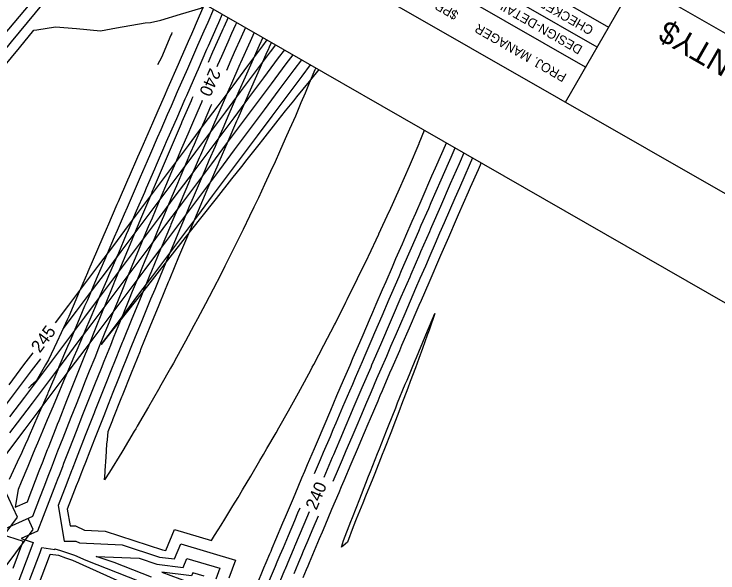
# Model space of a CAD drawing. Extents: x 1160447 to 1162032, y 616022 to 618272.
# Drawn here: x 1160997.8 to 1161139.1, y 616733 to 616845.1 of the extents above; entities that cross this region are included whole.
import ezdxf

# ---------------------------------------------------------------- set-up
doc = ezdxf.new("R2010")
doc.units = 0
for name, color, linetype in [('BORDER', 7, 'Continuous'), ('BRIDGE_TITLE', 7, 'Continuous'), ('D_Contours_Major', 7, 'Continuous'), ('D_Contours_Minor', 7, 'Continuous'), ('Plot Boundary_1', 7, 'Continuous')]:
    doc.layers.add(name, color=color, linetype=linetype)

msp = doc.modelspace()

# ---------------------------------------------------------------- linework, layer by layer
at = {"layer": 'BORDER'}
for p, q in [((1161303.72, 616715.44), (1160848.31, 616976.65)), ((1161108.53, 616827.39), (1161133.41, 616870.77)), ((1161274.24, 616764.57), (1161122.44, 616851.64))]:
    msp.add_line(p, q, dxfattribs=at)
for points in [[(1161041.29, 616886.02), (1161117.17, 616842.49)], [(1161114.86, 616838.45), (1161038.97, 616881.98)], [(1161112.54, 616834.41), (1161039.71, 616876.18)]]:
    msp.add_lwpolyline(points, dxfattribs=at)
at = {"layer": 'D_Contours_Major'}
for points in [[(1160975.33, 616809.76), (1160976.62, 616811.32), (1160979.81, 616815.18), (1160982.99, 616819.04), (1160986.17, 616822.9), (1160989.36, 616826.76), (1160992.55, 616830.62), (1160995.73, 616834.47), (1160998.92, 616838.33), (1161001.83, 616841.84), (1161002.43, 616841.94), (1161006.15, 616842.54), (1161010.36, 616842.17), (1161015.21, 616841.72), (1161018.4, 616842.3), (1161024.16, 616843.33), (1161025.22, 616843.37), (1161027.33, 616843.88), (1161031.24, 616845.06), (1161035.35, 616846.28), (1161036.36, 616846.96)], [(1161037.88, 616846.09), (1161036.7, 616843.4), (1161035.94, 616841.67), (1161034.66, 616838.77), (1161033.84, 616836.91), (1161032.63, 616834.13), (1161030.6, 616829.5), (1161029.34, 616826.6), (1161028.58, 616824.86), (1161027.28, 616821.88), (1161026.56, 616820.23), (1161025.22, 616817.15), (1161024.54, 616815.59), (1161023.17, 616812.4), (1161022.53, 616810.94), (1161021.13, 616807.7), (1161020.53, 616806.3), (1161019.93, 616804.92), (1161018.53, 616801.66), (1161017.94, 616800.3), (1161016.53, 616797.01), (1161015.96, 616795.69), (1161014.53, 616792.36), (1161013.98, 616791.07), (1161012.55, 616787.71), (1161012.01, 616786.46), (1161010.56, 616783.05), (1161009.01, 616779.41), (1161008.58, 616778.4), (1161006.83, 616774.29), (1161006.6, 616773.74), (1161004.74, 616769.34), (1161004.63, 616769.09), (1161004.53, 616768.86), (1161002.61, 616764.45), (1161000.9, 616760.5), (1161000.59, 616759.8), (1161000.1, 616758.66), (1160999.56, 616757.49), (1160999.38, 616757.1), (1160998.49, 616755.2), (1160996.89, 616751.74)], [(1161038.61, 616834.58), (1161038.76, 616834.9), (1161039.52, 616836.63), (1161040.8, 616839.52), (1161041.56, 616841.24), (1161042.34, 616842.97), (1161042.53, 616843.42)], [(1161048.6, 616839.94), (1161047.71, 616838.74), (1161044.72, 616834.73), (1161041.73, 616830.72), (1161038.74, 616826.71), (1161035.75, 616822.71), (1161032.76, 616818.7), (1161029.76, 616814.7), (1161026.77, 616810.69), (1161023.77, 616806.69), (1161020.77, 616802.69), (1161017.78, 616798.68), (1161014.78, 616794.68), (1161011.78, 616790.68), (1161008.77, 616786.68), (1161006.09, 616783.11)], [(1161059.02, 616833.96), (1161057.07, 616831.57), (1161054.54, 616828.46), (1161053.91, 616827.69), (1161052.27, 616825.66), (1161050.78, 616823.79), (1161047.68, 616819.86), (1161046.96, 616818.95), (1161044.58, 616815.94), (1161043.48, 616814.54), (1161041.48, 616812.01), (1161038.39, 616808.09), (1161035.29, 616804.16), (1161032.2, 616800.23), (1161029.11, 616796.3), (1161026.01, 616792.37), (1161022.92, 616788.44), (1161019.83, 616784.51), (1161018.66, 616783.02), (1161016.75, 616780.58), (1161015.35, 616778.79), (1161016.71, 616780.6), (1161019.71, 616784.6), (1161022.71, 616788.6), (1161025.71, 616792.6), (1161028.71, 616796.6), (1161031.71, 616800.61), (1161034.71, 616804.61), (1161037.7, 616808.61), (1161040.69, 616812.62), (1161043.69, 616816.62), (1161046.68, 616820.63), (1161049.67, 616824.64), (1161052.66, 616828.65), (1161055.65, 616832.66), (1161057.34, 616834.93)], [(1161035.61, 616827.74), (1161035.46, 616827.38), (1161034.71, 616825.65), (1161033.45, 616822.75), (1161032.7, 616821.02), (1161031.45, 616818.11), (1161030.21, 616815.22), (1161029.46, 616813.47), (1161028.23, 616810.58), (1161027.49, 616808.82), (1161026.74, 616807.06), (1161025.53, 616804.17), (1161024.78, 616802.39), (1161023.58, 616799.52), (1161022.83, 616797.71), (1161021.64, 616794.85), (1161020.47, 616792.02), (1161019.72, 616790.19), (1161018.57, 616787.38), (1161017.8, 616785.51), (1161017.04, 616783.63), (1161015.9, 616780.84), (1161014.79, 616778.08), (1161014.02, 616776.15), (1161012.93, 616773.43), (1161012.14, 616771.47), (1161011.35, 616769.47), (1161010.28, 616766.77), (1161009.23, 616764.12), (1161008.43, 616762.08), (1161007.62, 616760), (1161006.59, 616757.37), (1161006.18, 616756.32), (1161005.68, 616755.02), (1161005.26, 616753.95), (1161004.76, 616752.67), (1161003.79, 616750.14), (1161002.95, 616747.96), (1161001.54, 616744.28), (1160995.35, 616741.48)], [(1161088.13, 616817.26), (1161087.38, 616815.54), (1161087.15, 616815.03), (1161085.39, 616811), (1161083.4, 616806.46), (1161081.64, 616802.43), (1161081.42, 616801.92), (1161081.19, 616801.41), (1161079.44, 616797.38), (1161079.22, 616796.87), (1161077.46, 616792.83), (1161077.25, 616792.33), (1161075.49, 616788.28), (1161073.73, 616784.2), (1161073.53, 616783.73), (1161073.33, 616783.27), (1161071.57, 616779.18), (1161071.38, 616778.74), (1161069.61, 616774.63), (1161069.43, 616774.21), (1161067.66, 616770.07), (1161065.86, 616765.88), (1161065.71, 616765.52), (1161063.9, 616761.29), (1161063.76, 616760.96), (1161061.94, 616756.69), (1161061.82, 616756.4), (1161061.7, 616756.11), (1161060, 616752.11)], [(1161001.6, 616777.14), (1160999.76, 616774.69), (1160996.76, 616770.7)], [(1161057.09, 616745.23), (1161056.02, 616742.71), (1161054.14, 616738.25), (1161054.09, 616738.14), (1161054.07, 616738.08), (1161053.13, 616735.85), (1161052.18, 616733.6), (1161052.17, 616733.57), (1161052.15, 616733.51), (1161050.26, 616729)], [(1160992.71, 616729.7), (1161001.7, 616741.71), (1161000.68, 616743.9)], [(1160995.08, 616740.79), (1160999.65, 616739.35), (1160999.34, 616738.53), (1160997.56, 616733.84)], [(1161036.01, 616732.31), (1161033.72, 616732.98), (1161033.46, 616732.36), (1161027.47, 616733.11), (1161032.93, 616731.08)]]:
    msp.add_lwpolyline(points, dxfattribs=at)
at = {"layer": 'D_Contours_Minor'}
for points in [[(1160995.75, 616840.76), (1160998.94, 616844.62), (1161002.13, 616848.47), (1161005.32, 616852.32), (1161008.52, 616856.17), (1161011.71, 616860.03), (1161012.31, 616860.75)], [(1160973.79, 616811.03), (1160975.04, 616812.54), (1160978.22, 616816.4), (1160981.4, 616820.26), (1160984.59, 616824.12), (1160987.77, 616827.98), (1160990.96, 616831.83), (1160994.15, 616835.69), (1160997.34, 616839.55), (1161000.53, 616843.4), (1161003.72, 616847.25), (1161006.91, 616851.11), (1161010.1, 616854.96), (1161013.3, 616858.81), (1161014.07, 616859.74)], [(1161035.95, 616846.81), (1161034.82, 616844.23), (1161033.44, 616841.05), (1161032.81, 616839.58), (1161031.2, 616835.91), (1161030.78, 616834.95), (1161028.73, 616830.31), (1161027.96, 616828.55), (1161026.7, 616825.68), (1161025.61, 616823.2), (1161024.66, 616821.05), (1161023.26, 616817.84), (1161022.63, 616816.41), (1161020.92, 616812.48), (1161020.61, 616811.77), (1161018.71, 616807.41), (1161018.59, 616807.13), (1161018.48, 616806.87), (1161016.58, 616802.48), (1161016.53, 616802.35), (1161014.59, 616797.86), (1161014.58, 616797.83), (1161012.65, 616793.36), (1161012.57, 616793.18), (1161010.72, 616788.89), (1161010.57, 616788.53), (1161008.8, 616784.42), (1161008.57, 616783.88), (1161008.15, 616782.98), (1161006.45, 616779.28), (1161004.74, 616775.71), (1161004.18, 616774.74), (1161002.29, 616771.47), (1161001.23, 616770.47), (1161000.77, 616770.04)], [(1161039.63, 616845.09), (1161038.85, 616843.33), (1161038.53, 616842.59), (1161036.8, 616838.67), (1161036.49, 616837.96), (1161034.76, 616834.01), (1161034.46, 616833.33), (1161032.43, 616828.7), (1161032.12, 616827.99), (1161030.41, 616824.07), (1161030.09, 616823.33), (1161028.39, 616819.43), (1161028.06, 616818.67), (1161026.38, 616814.8), (1161026.03, 616813.99), (1161024.37, 616810.16), (1161024.01, 616809.32), (1161022.37, 616805.52), (1161020.75, 616801.76), (1161020.37, 616800.88), (1161018.77, 616797.15), (1161018.37, 616796.23), (1161016.79, 616792.54), (1161016.38, 616791.59), (1161014.82, 616787.94), (1161014.39, 616786.94), (1161012.86, 616783.34), (1161012.41, 616782.29), (1161011.93, 616781.16), (1161010.43, 616777.64), (1161009.87, 616776.32), (1161008.45, 616772.98), (1161007.79, 616771.42), (1161006.48, 616768.33), (1161005.69, 616766.45), (1161004.51, 616763.67), (1161003.57, 616761.43), (1161002.55, 616759.01), (1161002.03, 616757.77), (1161001.57, 616756.68), (1161001.01, 616755.33), (1161000.59, 616754.35), (1160999.26, 616751.16), (1160998.64, 616749.68), (1160998.07, 616746.13), (1161000.53, 616747.24), (1161001.09, 616748.7), (1161001.42, 616749.57), (1161002.91, 616753.42), (1161003.66, 616755.37), (1161003.82, 616755.77), (1161004.58, 616757.73), (1161004.74, 616758.13), (1161006.28, 616762.09), (1161006.58, 616762.83), (1161006.86, 616763.56), (1161008.43, 616767.53), (1161010.03, 616771.56), (1161010.29, 616772.23), (1161010.55, 616772.88), (1161012.17, 616776.92), (1161012.42, 616777.53), (1161014.06, 616781.6), (1161015.73, 616785.72), (1161015.96, 616786.28), (1161016.19, 616786.84), (1161017.87, 616790.96), (1161018.09, 616791.49), (1161019.8, 616795.63), (1161021.53, 616799.81), (1161021.74, 616800.3), (1161023.49, 616804.48), (1161023.69, 616804.96), (1161025.46, 616809.16), (1161025.65, 616809.61), (1161025.84, 616810.06), (1161027.62, 616814.26), (1161027.81, 616814.7), (1161029.61, 616818.91), (1161031.43, 616823.12), (1161031.61, 616823.55), (1161033.44, 616827.76), (1161033.62, 616828.18), (1161033.78, 616828.54)], [(1161040.79, 616844.42), (1161039.93, 616842.48), (1161039.73, 616842.05), (1161039.54, 616841.62), (1161037.69, 616837.43), (1161037.5, 616837.01), (1161036.78, 616835.38)], [(1161044.28, 616842.42), (1161043.39, 616840.43), (1161042.05, 616837.41), (1161041.35, 616835.82), (1161040.45, 616833.78)], [(1161046.02, 616841.42), (1161045.22, 616839.62), (1161043.3, 616835.3), (1161043.18, 616835.01), (1161041.27, 616830.69), (1161041.14, 616830.4), (1161039.12, 616825.78), (1161037.24, 616821.45), (1161037.12, 616821.16), (1161035.24, 616816.81), (1161035.12, 616816.53), (1161035, 616816.24), (1161033.14, 616811.89), (1161033.02, 616811.62), (1161031.17, 616807.25), (1161029.31, 616802.85), (1161029.21, 616802.61), (1161027.36, 616798.19), (1161027.26, 616797.95), (1161025.41, 616793.51), (1161025.33, 616793.3), (1161025.24, 616793.09), (1161023.4, 616788.64), (1161023.33, 616788.45), (1161021.49, 616783.97), (1161019.65, 616779.44), (1161019.6, 616779.3), (1161019.54, 616779.17), (1161017.71, 616774.63), (1161017.67, 616774.52), (1161015.84, 616769.94), (1161013.99, 616765.29), (1161013.98, 616765.26), (1161013.97, 616765.23), (1161012.65, 616761.88), (1161012.13, 616760.57), (1161012.12, 616760.55), (1161010.3, 616755.87), (1161009.41, 616753.59), (1161009.38, 616753.52), (1161009.36, 616753.45), (1161008.47, 616751.17), (1161008.4, 616750.99), (1161006.66, 616746.47), (1161007.87, 616739.35), (1161010.23, 616739.33), (1161010.96, 616738.99), (1161019.56, 616738.63), (1161027.05, 616736.15), (1161030.03, 616735.78), (1161031.29, 616738.77), (1161042.3, 616735.54), (1161040.92, 616731.93)], [(1161047.77, 616840.42), (1161047.05, 616838.81), (1161045.8, 616836.01), (1161045.01, 616834.21), (1161044.21, 616832.41), (1161042.98, 616829.6), (1161040.96, 616824.98), (1161039.73, 616822.16), (1161038.95, 616820.36), (1161038.17, 616818.55), (1161036.96, 616815.73), (1161036.17, 616813.91), (1161034.97, 616811.1), (1161033.79, 616808.31), (1161033, 616806.46), (1161031.84, 616803.7), (1161031.05, 616801.82), (1161029.9, 616799.08), (1161029.1, 616797.17), (1161028.3, 616795.24), (1161027.17, 616792.52), (1161026.07, 616789.85), (1161025.25, 616787.86), (1161024.17, 616785.23), (1161023.34, 616783.2), (1161022.5, 616781.13), (1161021.44, 616778.53), (1161020.42, 616776), (1161019.56, 616773.86), (1161018.68, 616771.67), (1161017.69, 616769.18), (1161016.73, 616766.76), (1161015.83, 616764.5), (1161014.9, 616762.15), (1161013.99, 616759.81), (1161013.04, 616757.4), (1161012.15, 616755.12), (1161011.72, 616754.01), (1161011.24, 616752.77), (1161010.75, 616751.52), (1161010.33, 616750.43), (1161009.33, 616747.85), (1161008.52, 616745.73), (1161009.09, 616742.39), (1161010.19, 616742.38), (1161011.98, 616741.54), (1161016.15, 616741.37), (1161027.62, 616737.57), (1161028.31, 616737.48), (1161030.07, 616741.66), (1161037.48, 616739.49), (1161038.1, 616740.48), (1161038.82, 616741.63), (1161039.4, 616742.57), (1161040.16, 616743.78), (1161041.77, 616746.42), (1161042.79, 616748.09), (1161043.7, 616749.61), (1161045.38, 616752.41), (1161047.2, 616755.5), (1161047.93, 616756.75), (1161048.6, 616757.9), (1161050.44, 616761.1), (1161051, 616762.09), (1161052.9, 616765.47), (1161054.92, 616769.12), (1161055.32, 616769.85), (1161057.38, 616773.66), (1161057.7, 616774.25), (1161058, 616774.81), (1161060.04, 616778.67), (1161062.14, 616782.74), (1161062.33, 616783.1), (1161064.45, 616787.28), (1161064.58, 616787.54), (1161064.7, 616787.8), (1161066.79, 616792.01), (1161068.89, 616796.37), (1161068.95, 616796.49), (1161071.04, 616800.92), (1161071.08, 616800.99), (1161073.14, 616805.47), (1161073.16, 616805.51), (1161073.17, 616805.55), (1161075.2, 616810.04), (1161077.19, 616814.59), (1161079.14, 616819.13), (1161079.15, 616819.16), (1161080.24, 616821.79)], [(1161029.52, 616841.41), (1161029.41, 616841.08), (1161029.31, 616840.83), (1161027.46, 616836.4), (1161026.66, 616834.93)], [(1161007.69, 616781.91), (1161010.36, 616785.47), (1161013.36, 616789.47), (1161016.36, 616793.47), (1161019.36, 616797.47), (1161022.36, 616801.47), (1161025.36, 616805.47), (1161028.36, 616809.47), (1161031.35, 616813.48), (1161034.34, 616817.48), (1161037.34, 616821.49), (1161040.33, 616825.5), (1161043.32, 616829.5), (1161046.31, 616833.51), (1161049.3, 616837.52), (1161050.35, 616838.93)], [(1161058.39, 616834.32), (1161058.2, 616833.87), (1161057.09, 616831.22), (1161056.27, 616829.24), (1161055.42, 616827.26), (1161054.3, 616824.63), (1161053.15, 616822.02), (1161052.28, 616820.04), (1161051.11, 616817.43), (1161050.23, 616815.46), (1161049.33, 616813.53), (1161048.13, 616810.91), (1161046.87, 616808.25), (1161045.99, 616806.37), (1161045.1, 616804.54), (1161043.8, 616801.84), (1161042.43, 616799.07), (1161041.58, 616797.34), (1161040.14, 616794.49), (1161039.31, 616792.85), (1161037.79, 616789.91), (1161037, 616788.38), (1161036.24, 616786.93), (1161034.65, 616783.92), (1161033.94, 616782.6), (1161032.25, 616779.48), (1161030.42, 616776.16), (1161029.81, 616775.06), (1161029.24, 616774.03), (1161027.33, 616770.65), (1161026.84, 616769.79), (1161024.81, 616766.26), (1161022.56, 616762.42), (1161022.25, 616761.88), (1161021.95, 616761.39), (1161019.64, 616757.51), (1161019.46, 616757.22), (1161016.98, 616753.17), (1161016.02, 616751.61), (1161016.1, 616753.09), (1161016.12, 616753.51), (1161016.31, 616756.22), (1161016.49, 616758.79), (1161016.57, 616759.65), (1161016.73, 616761.31), (1161017.67, 616763.71), (1161017.68, 616763.74), (1161019.5, 616768.32), (1161019.54, 616768.42), (1161019.58, 616768.53), (1161021.41, 616773.1), (1161023.2, 616777.55), (1161023.29, 616777.77), (1161023.38, 616777.99), (1161025.19, 616782.43), (1161026.96, 616786.77), (1161027.09, 616787.09), (1161028.86, 616791.39), (1161029.01, 616791.75), (1161029.16, 616792.11), (1161030.94, 616796.39), (1161032.71, 616800.61), (1161032.89, 616801.04), (1161034.65, 616805.23), (1161034.84, 616805.68), (1161036.61, 616809.84), (1161036.81, 616810.31), (1161037.01, 616810.79), (1161038.79, 616814.94), (1161039, 616815.43), (1161040.78, 616819.56), (1161042.57, 616823.68), (1161042.79, 616824.18), (1161044.81, 616828.79), (1161045.03, 616829.3), (1161046.84, 616833.4), (1161048.66, 616837.52), (1161048.88, 616838), (1161049.09, 616838.49), (1161049.51, 616839.42)], [(1161052.1, 616837.93), (1161050.88, 616836.31), (1161047.9, 616832.3), (1161044.91, 616828.29), (1161041.92, 616824.28), (1161038.92, 616820.27), (1161035.93, 616816.27), (1161032.94, 616812.26), (1161029.94, 616808.26), (1161026.95, 616804.25), (1161023.95, 616800.25), (1161020.95, 616796.25), (1161017.95, 616792.25), (1161014.95, 616788.25), (1161011.95, 616784.25), (1161008.95, 616780.25), (1161005.94, 616776.26), (1161002.94, 616772.26), (1160999.93, 616768.26), (1160996.92, 616764.27)], [(1160997.01, 616761.06), (1160998.51, 616763.05), (1161001.52, 616767.05), (1161004.52, 616771.04), (1161007.53, 616775.04), (1161010.53, 616779.04), (1161013.54, 616783.04), (1161016.54, 616787.03), (1161019.54, 616791.03), (1161022.54, 616795.03), (1161025.54, 616799.04), (1161028.53, 616803.04), (1161031.53, 616807.04), (1161034.53, 616811.05), (1161037.52, 616815.05), (1161040.51, 616819.06), (1161043.5, 616823.06), (1161046.49, 616827.07), (1161049.48, 616831.08), (1161052.47, 616835.09), (1161053.84, 616836.93)], [(1160994.08, 616753.85), (1160998.59, 616759.84), (1161000.1, 616761.84), (1161003.11, 616765.83), (1161006.11, 616769.83), (1161009.12, 616773.82), (1161012.12, 616777.82), (1161015.12, 616781.82), (1161018.13, 616785.82), (1161021.13, 616789.82), (1161024.13, 616793.82), (1161027.12, 616797.82), (1161030.12, 616801.82), (1161033.12, 616805.83), (1161036.11, 616809.83), (1161039.11, 616813.83), (1161042.1, 616817.84), (1161045.09, 616821.85), (1161048.08, 616825.85), (1161051.07, 616829.86), (1161054.06, 616833.87), (1161055.59, 616835.93)], [(1161037.45, 616826.94), (1161037.29, 616826.58), (1161035.97, 616823.55), (1161035.28, 616821.95), (1161033.97, 616818.91), (1161033.28, 616817.32), (1161032.6, 616815.73), (1161031.3, 616812.68), (1161030.63, 616811.1), (1161029.33, 616808.04), (1161028.03, 616804.96), (1161027.37, 616803.39), (1161026.07, 616800.29), (1161025.42, 616798.74), (1161024.12, 616795.61), (1161023.48, 616794.08), (1161022.86, 616792.56), (1161021.56, 616789.41), (1161020.95, 616787.91), (1161019.65, 616784.74), (1161018.34, 616781.53), (1161017.75, 616780.07), (1161017.17, 616778.62), (1161015.86, 616775.39), (1161015.3, 616773.98), (1161013.99, 616770.71), (1161012.67, 616767.38), (1161012.13, 616766.02), (1161011.6, 616764.67), (1161010.28, 616761.32), (1161008.95, 616757.91), (1161008.44, 616756.62), (1161007.77, 616754.9), (1161007.53, 616754.27), (1161006.86, 616752.54), (1161006.62, 616751.92), (1161006.15, 616750.7), (1161004.8, 616747.21), (1161002.55, 616741.32), (1160999.28, 616739.84), (1161001.69, 616739.08), (1161001.2, 616737.79), (1160998.4, 616730.39)], [(1161046.55, 616730.48), (1161048, 616733.96), (1161048.46, 616735.06), (1161049.18, 616736.78), (1161049.42, 616737.35), (1161049.67, 616737.93), (1161050.39, 616739.64), (1161051.8, 616742.99), (1161052.31, 616744.21), (1161053.71, 616747.51), (1161054.25, 616748.79), (1161055.62, 616752.03), (1161056.18, 616753.36), (1161056.76, 616754.71), (1161058.12, 616757.93), (1161058.72, 616759.33), (1161060.07, 616762.49), (1161061.39, 616765.6), (1161062.01, 616767.06), (1161062.65, 616768.54), (1161063.97, 616771.62), (1161065.27, 616774.66), (1161065.92, 616776.18), (1161067.22, 616779.19), (1161067.88, 616780.74), (1161069.17, 616783.73), (1161069.85, 616785.3), (1161070.53, 616786.89), (1161071.82, 616789.86), (1161072.51, 616791.46), (1161073.79, 616794.41), (1161074.49, 616796.03), (1161075.77, 616798.96), (1161076.48, 616800.59), (1161077.75, 616803.51), (1161078.46, 616805.15), (1161079.73, 616808.06), (1161081.72, 616812.61), (1161082.44, 616814.24), (1161083.72, 616817.15), (1161084.43, 616818.78), (1161084.64, 616819.26)], [(1161058.16, 616752.89), (1161059.36, 616755.72), (1161059.97, 616757.16), (1161061.32, 616760.33), (1161061.91, 616761.73), (1161062.5, 616763.1), (1161063.86, 616766.29), (1161065.25, 616769.53), (1161065.81, 616770.85), (1161066.37, 616772.15), (1161067.77, 616775.41), (1161068.31, 616776.67), (1161069.73, 616779.96), (1161070.26, 616781.2), (1161071.69, 616784.52), (1161073.13, 616787.86), (1161073.66, 616789.07), (1161075.11, 616792.43), (1161075.63, 616793.62), (1161077.09, 616796.99), (1161077.6, 616798.17), (1161079.07, 616801.55), (1161079.58, 616802.72), (1161081.06, 616806.1), (1161081.57, 616807.26), (1161083.55, 616811.8), (1161085.04, 616815.18), (1161085.55, 616816.35), (1161086.39, 616818.26)], [(1161089.88, 616816.26), (1161089.21, 616814.73), (1161088.3, 616812.68), (1161087.22, 616810.2), (1161086.32, 616808.14), (1161085.23, 616805.66), (1161084.15, 616803.18), (1161083.25, 616801.12), (1161082.36, 616799.07), (1161081.28, 616796.58), (1161080.39, 616794.54), (1161079.3, 616792.04), (1161078.42, 616790.01), (1161077.33, 616787.5), (1161076.24, 616784.97), (1161075.37, 616782.95), (1161074.51, 616780.95), (1161073.41, 616778.4), (1161072.56, 616776.42), (1161071.45, 616773.85), (1161070.61, 616771.9), (1161069.5, 616769.3), (1161068.37, 616766.67), (1161067.55, 616764.75), (1161066.41, 616762.08), (1161065.61, 616760.19), (1161064.46, 616757.49), (1161063.67, 616755.64), (1161062.89, 616753.81), (1161061.84, 616751.33)], [(1161055.88, 616732.07), (1161056.55, 616733.66), (1161056.84, 616734.36), (1161057.13, 616735.04), (1161057.8, 616736.64), (1161059.17, 616739.89), (1161059.72, 616741.2), (1161060.27, 616742.48), (1161061.65, 616745.76), (1161063.06, 616749.1), (1161063.58, 616750.32), (1161064.09, 616751.51), (1161065.52, 616754.87), (1161066.97, 616758.29), (1161067.45, 616759.43), (1161068.93, 616762.88), (1161069.4, 616763.98), (1161070.89, 616767.46), (1161071.34, 616768.53), (1161071.8, 616769.58), (1161073.29, 616773.08), (1161073.74, 616774.1), (1161075.25, 616777.62), (1161075.68, 616778.63), (1161077.21, 616782.17), (1161078.75, 616785.73), (1161079.17, 616786.71), (1161079.59, 616787.68), (1161081.14, 616791.25), (1161081.55, 616792.2), (1161083.11, 616795.79), (1161083.52, 616796.73), (1161085.09, 616800.33), (1161086.66, 616803.93), (1161087.07, 616804.86), (1161089.05, 616809.4), (1161089.46, 616810.33), (1161091.04, 616813.93), (1161091.45, 616814.86), (1161091.62, 616815.26)], [(1160973.75, 616737.36), (1160974.23, 616737.57), (1160971.67, 616740.01), (1160970.16, 616741.18), (1160969.37, 616741.94), (1160962.32, 616747.44), (1160957.4, 616752.62), (1160953.21, 616755.98), (1160947.06, 616763.5), (1160958.56, 616754.13), (1160964.18, 616749.97), (1160971.25, 616744.39), (1160972.77, 616743.28), (1160973.64, 616742.59), (1160980.01, 616739.43), (1160989, 616751.45), (1160988.4, 616756.28), (1160989.32, 616757.5), (1160993.83, 616763.49), (1160995.34, 616765.49), (1160998.34, 616769.48), (1161001.35, 616773.48), (1161003.2, 616775.94)], [(1160989.54, 616732.13), (1160998.52, 616744.15), (1160995.03, 616751.63)], [(1161049.13, 616731.48), (1161050.32, 616734.32), (1161050.67, 616735.16), (1161051.28, 616736.6), (1161051.89, 616738.07), (1161052.24, 616738.89), (1161052.92, 616740.5), (1161054.17, 616743.46), (1161054.82, 616745.02), (1161055.24, 616746.01)], [(1161054.03, 616732.82), (1161054.37, 616733.63), (1161054.99, 616735.11), (1161055.6, 616736.56), (1161055.95, 616737.39), (1161056.65, 616739.07), (1161057.87, 616741.95), (1161058.93, 616744.45)], [(1160999.49, 616727.63), (1161002.72, 616736.17), (1161003.06, 616737.05), (1161003.44, 616738.05), (1161006.01, 616737.65), (1161006.05, 616737.82), (1161007.13, 616737.47), (1161007.78, 616737.26), (1161009.98, 616736.53), (1161012.24, 616735.52), (1161024.84, 616730.59)], [(1161002.73, 616730.53), (1161004.92, 616736.32), (1161005.09, 616736.76), (1161006.74, 616736.51), (1161008.19, 616735.96), (1161009.57, 616735.51), (1161021.85, 616730)], [(1161025.44, 616732.11), (1161017.96, 616735.04), (1161014.69, 616736.11), (1161014.32, 616736.25), (1161022.96, 616735.9), (1161026.49, 616734.73), (1161031.75, 616734.07), (1161032.51, 616735.88), (1161039.16, 616733.92), (1161038.32, 616731.74)]]:
    msp.add_lwpolyline(points, dxfattribs=at)
msp.add_lwpolyline([(1161080.36, 616780.41), (1161080.51, 616780.76), (1161082.32, 616785.02), (1161081.14, 616781.68), (1161080.77, 616780.65), (1161079.8, 616777.97), (1161079.08, 616776), (1161078.38, 616774.09), (1161077.37, 616771.36), (1161076.87, 616770.04), (1161075.63, 616766.73), (1161075.27, 616765.81), (1161073.86, 616762.12), (1161073.57, 616761.38), (1161072.06, 616757.51), (1161071.75, 616756.75), (1161070.23, 616752.92), (1161069.82, 616751.91), (1161068.37, 616748.35), (1161067.81, 616746.93), (1161066.53, 616743.76), (1161065.93, 616742.19), (1161064.76, 616739.15), (1161063.92, 616738.42), (1161063.59, 616738.16), (1161063.96, 616739.47), (1161065.46, 616743.28), (1161065.78, 616744.07), (1161067.24, 616747.84), (1161067.56, 616748.68), (1161068.99, 616752.36), (1161069.35, 616753.29), (1161070.77, 616756.9), (1161071.16, 616757.89), (1161072.59, 616761.49), (1161072.99, 616762.48), (1161074.46, 616766.12), (1161074.83, 616767.06), (1161076.37, 616770.81), (1161076.71, 616771.64), (1161078.34, 616775.57), (1161078.6, 616776.2)], close=True, dxfattribs=at)
at = {"layer": 'Plot Boundary_1'}
msp.add_lwpolyline([(1160500.57, 616331.28), (1160855.78, 616950.54), (1161275.71, 616709.67), (1160920.5, 616090.41)], close=True, dxfattribs=at)

# ---------------------------------------------------------------- texts
at = {"layer": 'BORDER'}
for s, p in [('$PROJMANAGER$', (1161087.2, 616845.42)), ('CHECKED-REVIEWED', (1161114.33, 616842.4)), ('DESIGN-DETAILED', (1161112.1, 616838.53)), ('PROJ. MANAGER', (1161108.91, 616832.96))]:
    msp.add_text(s, height=1.8637, rotation=150.1613, dxfattribs=at).set_placement(p)
at = {"layer": 'BRIDGE_TITLE'}
msp.add_text('$COUNTY$', height=4.536, rotation=150.1613, dxfattribs=at).set_placement((1161157.07, 616827.92))
at = {"layer": 'D_Contours_Major'}
for s, rotation, p in [('240', 246.3235, (1161037.18, 616834.41)), ('245', 53.0696, (1161003.02, 616776.96)), ('240', 67.0545, (1161058.52, 616745.43))]:
    msp.add_text(s, height=2.49, rotation=rotation, dxfattribs=at).set_placement(p)

doc.saveas('drawing.dxf')
